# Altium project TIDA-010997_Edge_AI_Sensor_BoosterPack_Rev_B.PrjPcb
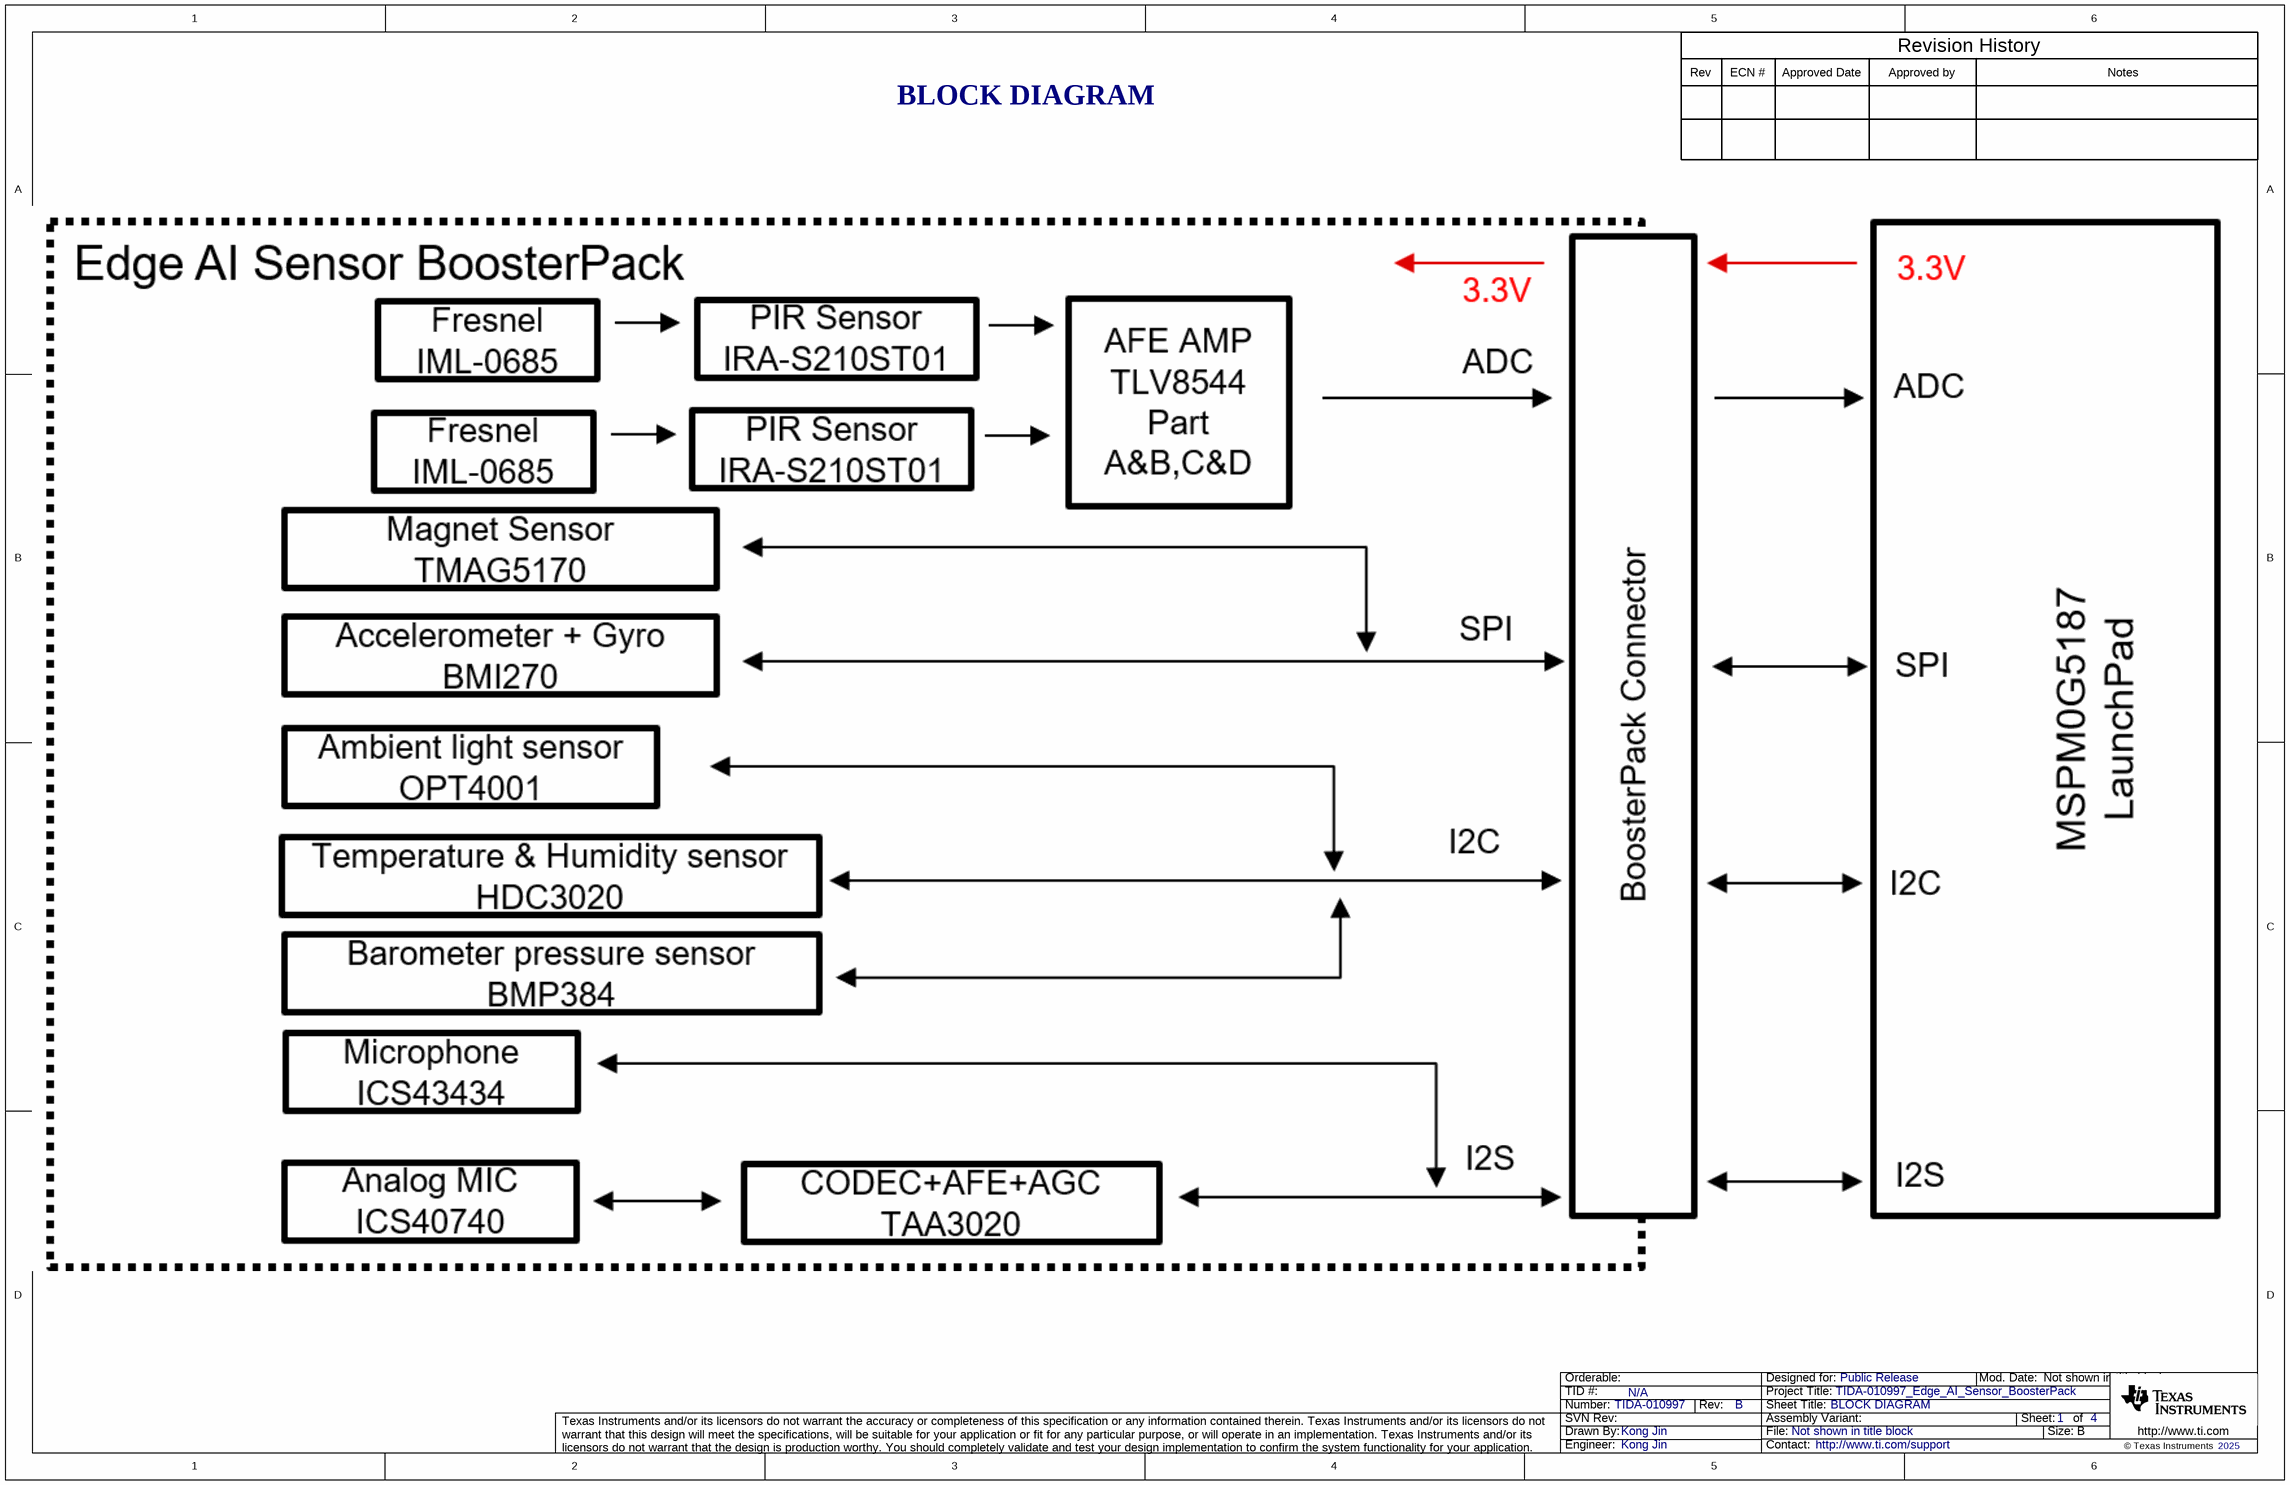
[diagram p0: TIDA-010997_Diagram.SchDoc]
CopyrightYear: 2025; PCB_Layout: Kong Jin; PCB_Rev: B; PRJ_Customer: Public Release; PRJ_Engineer: Kong Jin; PRJ_Number: TIDA-010997; PRJ_Title: TIDA-010997_Edge_AI_Sensor_BoosterPack; SCH_Rev: B; TechSupport: http://www.ti.com/support; TID: N/A
4 sheets, 121 parts. Net scope: global (net labels, ports and power ports of the same name join across sheets).
Board file: TIDA-010997_PCB.PcbDoc
Sheets:
  TIDA-010997_Diagram.SchDoc
  TIDA-010997_Connector.SchDoc
  TIDA-010997_Sensors.SchDoc
  TIDA-010997_Audio_Air_pressure.SchDoc

## Sheet TIDA-010997_Diagram.SchDoc: BLOCK DIAGRAM
size 431 x 279 mm; Date: Not shown in title block; ApprovedBy: Not shown in title block; CheckedBy: Not shown in title block; Author: Not shown in title block; CompanyName: Not shown in title block; DrawnBy: Kong Jin; Organization: Not shown in title block; Address1: Not shown in title block; Address2: Not shown in title block; Address3: Not shown in title block; Address4: Not shown in title block; DocumentNumber: 1; Revision: Use project parameter SCH_Rev; SheetNumber: 1; SheetTotal: 4; PageSetup: Record=PageOptions¦CenterHorizontal=True¦CenterVertical=True¦PrintScale=1.00¦XCorrection=1.00¦YCorrection=1.00¦PrintKind=0¦BorderSize=5000000¦LeftOffset=0¦BottomOffset=0¦Orientation=2¦PaperLength=1000¦PaperWidth=1000¦Scale=100¦PaperSource=15¦PrintQuality=600¦MediaType=1¦DitherType=10¦PaperKind=Letter¦PrintScaleMode=1

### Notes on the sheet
- Rev
- ECN #
- Approved Date
- Approved by
- Revision History
- Notes
- BLOCK DIAGRAM

## Sheet TIDA-010997_Connector.SchDoc: Connector
size 431 x 279 mm; Date: Not shown in title block; ApprovedBy: Not shown in title block; CheckedBy: Not shown in title block; Author: Not shown in title block; CompanyName: Not shown in title block; DrawnBy: Kong Jin; Engineer: Not shown in title block; Organization: Not shown in title block; Address1: Not shown in title block; Address2: Not shown in title block; Address3: Not shown in title block; Address4: Not shown in title block; DocumentNumber: 2; Revision: Use project parameter SCH_Rev; SheetNumber: 2; SheetTotal: 4; PageSetup: Record=PageOptions¦CenterHorizontal=True¦CenterVertical=True¦PrintScale=1.00¦XCorrection=1.00¦YCorrection=1.00¦PrintKind=0¦BorderSize=5000000¦LeftOffset=0¦BottomOffset=0¦Orientation=2¦PaperLength=1000¦PaperWidth=1000¦Scale=100¦PaperSource=15¦PrintQuality=600¦MediaType=1¦DitherType=10¦PaperKind=Letter¦PrintScaleMode=1
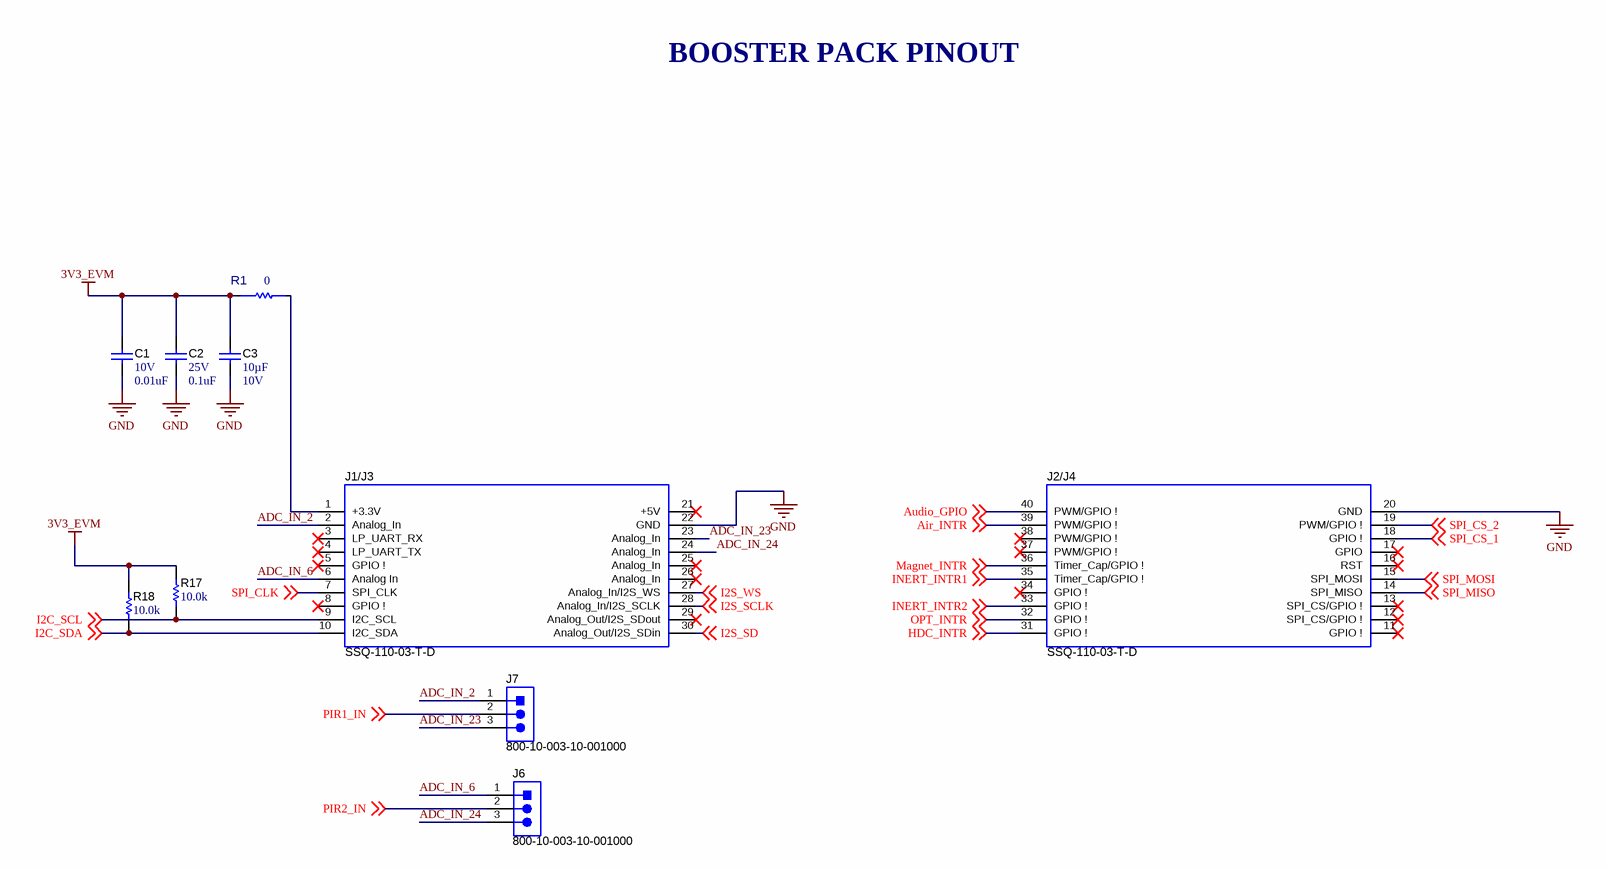
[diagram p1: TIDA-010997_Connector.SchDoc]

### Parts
C1  VDC_V: 10V  ValueDisplayed: 0.01uF  [0402]  (hidden comment: GRM155R61A103KA01D)
C2  VDC_V: 25V  ValueDisplayed: 0.1uF  [0603]  (hidden comment: 06033D104KAT2A)
C3  Cap_F: 10µF  VDC_V: 10V  [0805_HV]  (hidden comment: C2012X7R1A106K125AC)
J1/J3  SSQ-110-03-T-D  [BoosterPack_40pin_J1J3]
J2/J4  SSQ-110-03-T-D  [BoosterPack_40pin_J2J4]
J6  800-10-003-10-001000  [Mill-Max_800-10-003-10-001000]
J7  800-10-003-10-001000  [Mill-Max_800-10-003-10-001000]
R1  value 0  [FP-HCJ0805ZT0R00_0805-MFG]  (hidden comment: HCJ0805ZT0R00)
R17  ValueDisplayed: 10.0k  [0402]  (hidden comment: AC0402FR-0710KL)
R18  ValueDisplayed: 10.0k  [0402]  (hidden comment: AC0402FR-0710KL)

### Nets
3V3_EVM: C1.1 C2.1 C3.1 R1.1 R17.2 R18.2
GND: C1.2 C2.2 C3.2 J1/J3.22(GND) J2/J4.20(GND)
ADC_IN_2: J1/J3.2(Analog_In) J7.1
ADC_IN_6: J1/J3.6(Analog_In) J6.1
ADC_IN_23: J1/J3.23(Analog_In) J7.3
ADC_IN_24: J1/J3.24(Analog_In) J6.3
Air_INTR: J2/J4.39(PWM/GPIO_!) ; off-sheet Air_INTR
Audio_GPIO: J2/J4.40(PWM/GPIO_!) ; off-sheet Audio_GPIO
HDC_INTR: J2/J4.31(GPIO_!) ; off-sheet HDC_INTR
I2C_SCL: J1/J3.9(I2C_SCL) R17.1 ; off-sheet I2C_SCL
I2C_SDA: J1/J3.10(I2C_SDA) R18.1 ; off-sheet I2C_SDA
I2S_SCLK: J1/J3.28(Analog_In/I2S_SCLK) ; off-sheet I2S_SCLK
I2S_SD: J1/J3.30(Analog_Out/I2S_SDin) ; off-sheet I2S_SD
I2S_WS: J1/J3.27(Analog_In/I2S_WS) ; off-sheet I2S_WS
INERT_INTR1: J2/J4.35(Timer_Cap/GPIO_!) ; off-sheet INERT_INTR1
INERT_INTR2: J2/J4.33(GPIO_!) ; off-sheet INERT_INTR2
Magnet_INTR: J2/J4.36(Timer_Cap/GPIO_!) ; off-sheet Magnet_INTR
OPT_INTR: J2/J4.32(GPIO_!) ; off-sheet OPT_INTR
PIR1_IN: J7.2 ; off-sheet PIR1_IN
PIR2_IN: J6.2 ; off-sheet PIR2_IN
SPI_CLK: J1/J3.7(SPI_CLK) ; off-sheet SPI_CLK
SPI_CS_1: J2/J4.18(GPIO_!) ; off-sheet SPI_CS_1
SPI_CS_2: J2/J4.19(PWM/GPIO_!) ; off-sheet SPI_CS_2
SPI_MISO: J2/J4.14(SPI_MISO) ; off-sheet SPI_MISO
SPI_MOSI: J2/J4.15(SPI_MOSI) ; off-sheet SPI_MOSI
NetJ1/J3_1: J1/J3.1(+3.3V) R1.2

Not connected (* = marked no-connect by the designer): J1/J3 3(LP_UART_RX)* 4(LP_UART_TX)* 5(GPIO_!)* 8(GPIO_!)* 21(+5V)* 25(Analog_In)* 26(Analog_In)* 29(Analog_Out/I2S_SDout)*; J2/J4 11(GPIO_!)* 12(SPI_CS/GPIO_!)* 13(SPI_CS/GPIO_!)* 16(RST)* 17(GPIO)* 34(GPIO_!)* 37(PWM/GPIO_!)* 38(PWM/GPIO_!)*

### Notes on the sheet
- BOOSTER PACK PINOUT

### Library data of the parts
C1 = CMP-0006561-2: CAP, CERM, 0.01 uF, 10 V, +/- 10%, X5R, 0402; Manufacturer: MuRata; TaMin_C: -55°C; Polarized: N; SizeAreaWB_mm2: 3; Value1: Unknown; U/M: EA; Value: 0.01uF; TaMax_C: 85°C; SizeZ_mm: 0.6; SizeX_mm: 1; SizeY_mm: 0.5; Cap_F: 10nF; AEC Category: Q200
C2 = CMP-0006758-5: CAP, CERM, 0.1 uF, 25 V, +/- 10%, X5R, 0603; Manufacturer: AVX; TaMin_C: -55°C; ESR_ohm: 48m; Polarized: N; SizeAreaWB_mm2: 4.68; Value1: 0.048 ohm; U/M: EA; Value: 0.1uF; TaMax_C: 85°C; SizeZ_mm: 1; SizeX_mm: 1.6; SizeY_mm: 0.8; SizeArea_mm2: 1.28; Cap_F: 100nF; IRMS_A: 530mA; AEC Category: Q200
C3 = CMP-0007863-2: CAP, CERM, 10 uF, 10 V, +/- 10%, X7R, 0805; Manufacturer: TDK; TaMin_C: -55°C; ESR_ohm: 1.063m; Polarized: N; SizeAreaWB_mm2: 6.75; Value1: 0.001063 ohm; U/M: EA; Value: 10uF; TaMax_C: 125°C; SizeZ_mm: 1.45; SizeX_mm: 2; SizeY_mm: 1.25; Cap_Case: 0805; SizeArea_mm2: 2.5; IRMS_A: 6.3291A; AEC Category: Q200
J1/J3 = CMP-0003837-4: Receptacle, 2.54mm, 10x2, Tin, TH; Alternate PartNumber: CRD-081413-A-G; Manufacturer: Samtec; Alternate Manufacturer: Major League Electronics; Note: Booster Pack 40 pin J1 and J3; Green_Lifecycle: Active; Green_REACh: Incomplete
J2/J4 = CMP-0078266-4: Receptacle, 2.54mm, 10x2, Tin, TH; Alternate PartNumber: CRD-081413-A-G; Manufacturer: Samtec; Alternate Manufacturer: Major League Electronics; Note: Booster Pack 40 pin J2 and J4; Green_REACh: Incomplete; Green_Lifecycle: Active
J6 J7 = CMP-0055086-1: Header, 100mil, 3x1, TH; Manufacturer: Mill-Max; CNHeader: TRUE; Green_Lifecycle: Active; Green_REACh: Passed; CT: FALSE
R1 = CMP-0091603-1: 0 Ohms Jumper 0.5W, 1/2W Chip Resistor 0805 (2012 Metric) Automotive AEC-Q200 Metal Foil; Manufacturer: Stackpole; SizeZ_mm: 0.85mm; Power: 500mW; AEC Grade: Grade 0; AEC Qualified: Yes
R17 R18 = CMP-0077731-1: RES, 10.0 k, 1%, 0.063 W, AEC-Q200 Grade 0, 0402; Manufacturer: Yageo America; Power_W: 63mW; TempCo: 100 ppm/C; Value_Code: 10k0; U/M: EA; Value: 10.0k; EIA_Code: E96; Res_ohm: 10k; SizeX_mm: 1.0; SizeY_mm: 0.5; SizeZ_mm: 0.6; Value2: 0.063W; AEC Qualified: Y; VDC_V: 50V; AEC Grade: 0; AEC Category: Q200

## Sheet TIDA-010997_Sensors.SchDoc: Sensors
size 431 x 279 mm; Date: Not shown in title block; ApprovedBy: Not shown in title block; CheckedBy: Not shown in title block; Author: Not shown in title block; CompanyName: Not shown in title block; DrawnBy: Kong Jin; Engineer: Not shown in title block; Organization: Not shown in title block; Address1: Not shown in title block; Address2: Not shown in title block; Address3: Not shown in title block; Address4: Not shown in title block; DocumentNumber: 3; Revision: Use project parameter SCH_Rev; SheetNumber: 3; SheetTotal: 4; PageSetup: Record=PageOptions¦CenterHorizontal=True¦CenterVertical=True¦PrintScale=1.00¦XCorrection=1.00¦YCorrection=1.00¦PrintKind=0¦BorderSize=5000000¦LeftOffset=0¦BottomOffset=0¦Orientation=2¦PaperLength=1000¦PaperWidth=1000¦Scale=100¦PaperSource=15¦PrintQuality=600¦MediaType=1¦DitherType=10¦PaperKind=Letter¦PrintScaleMode=1
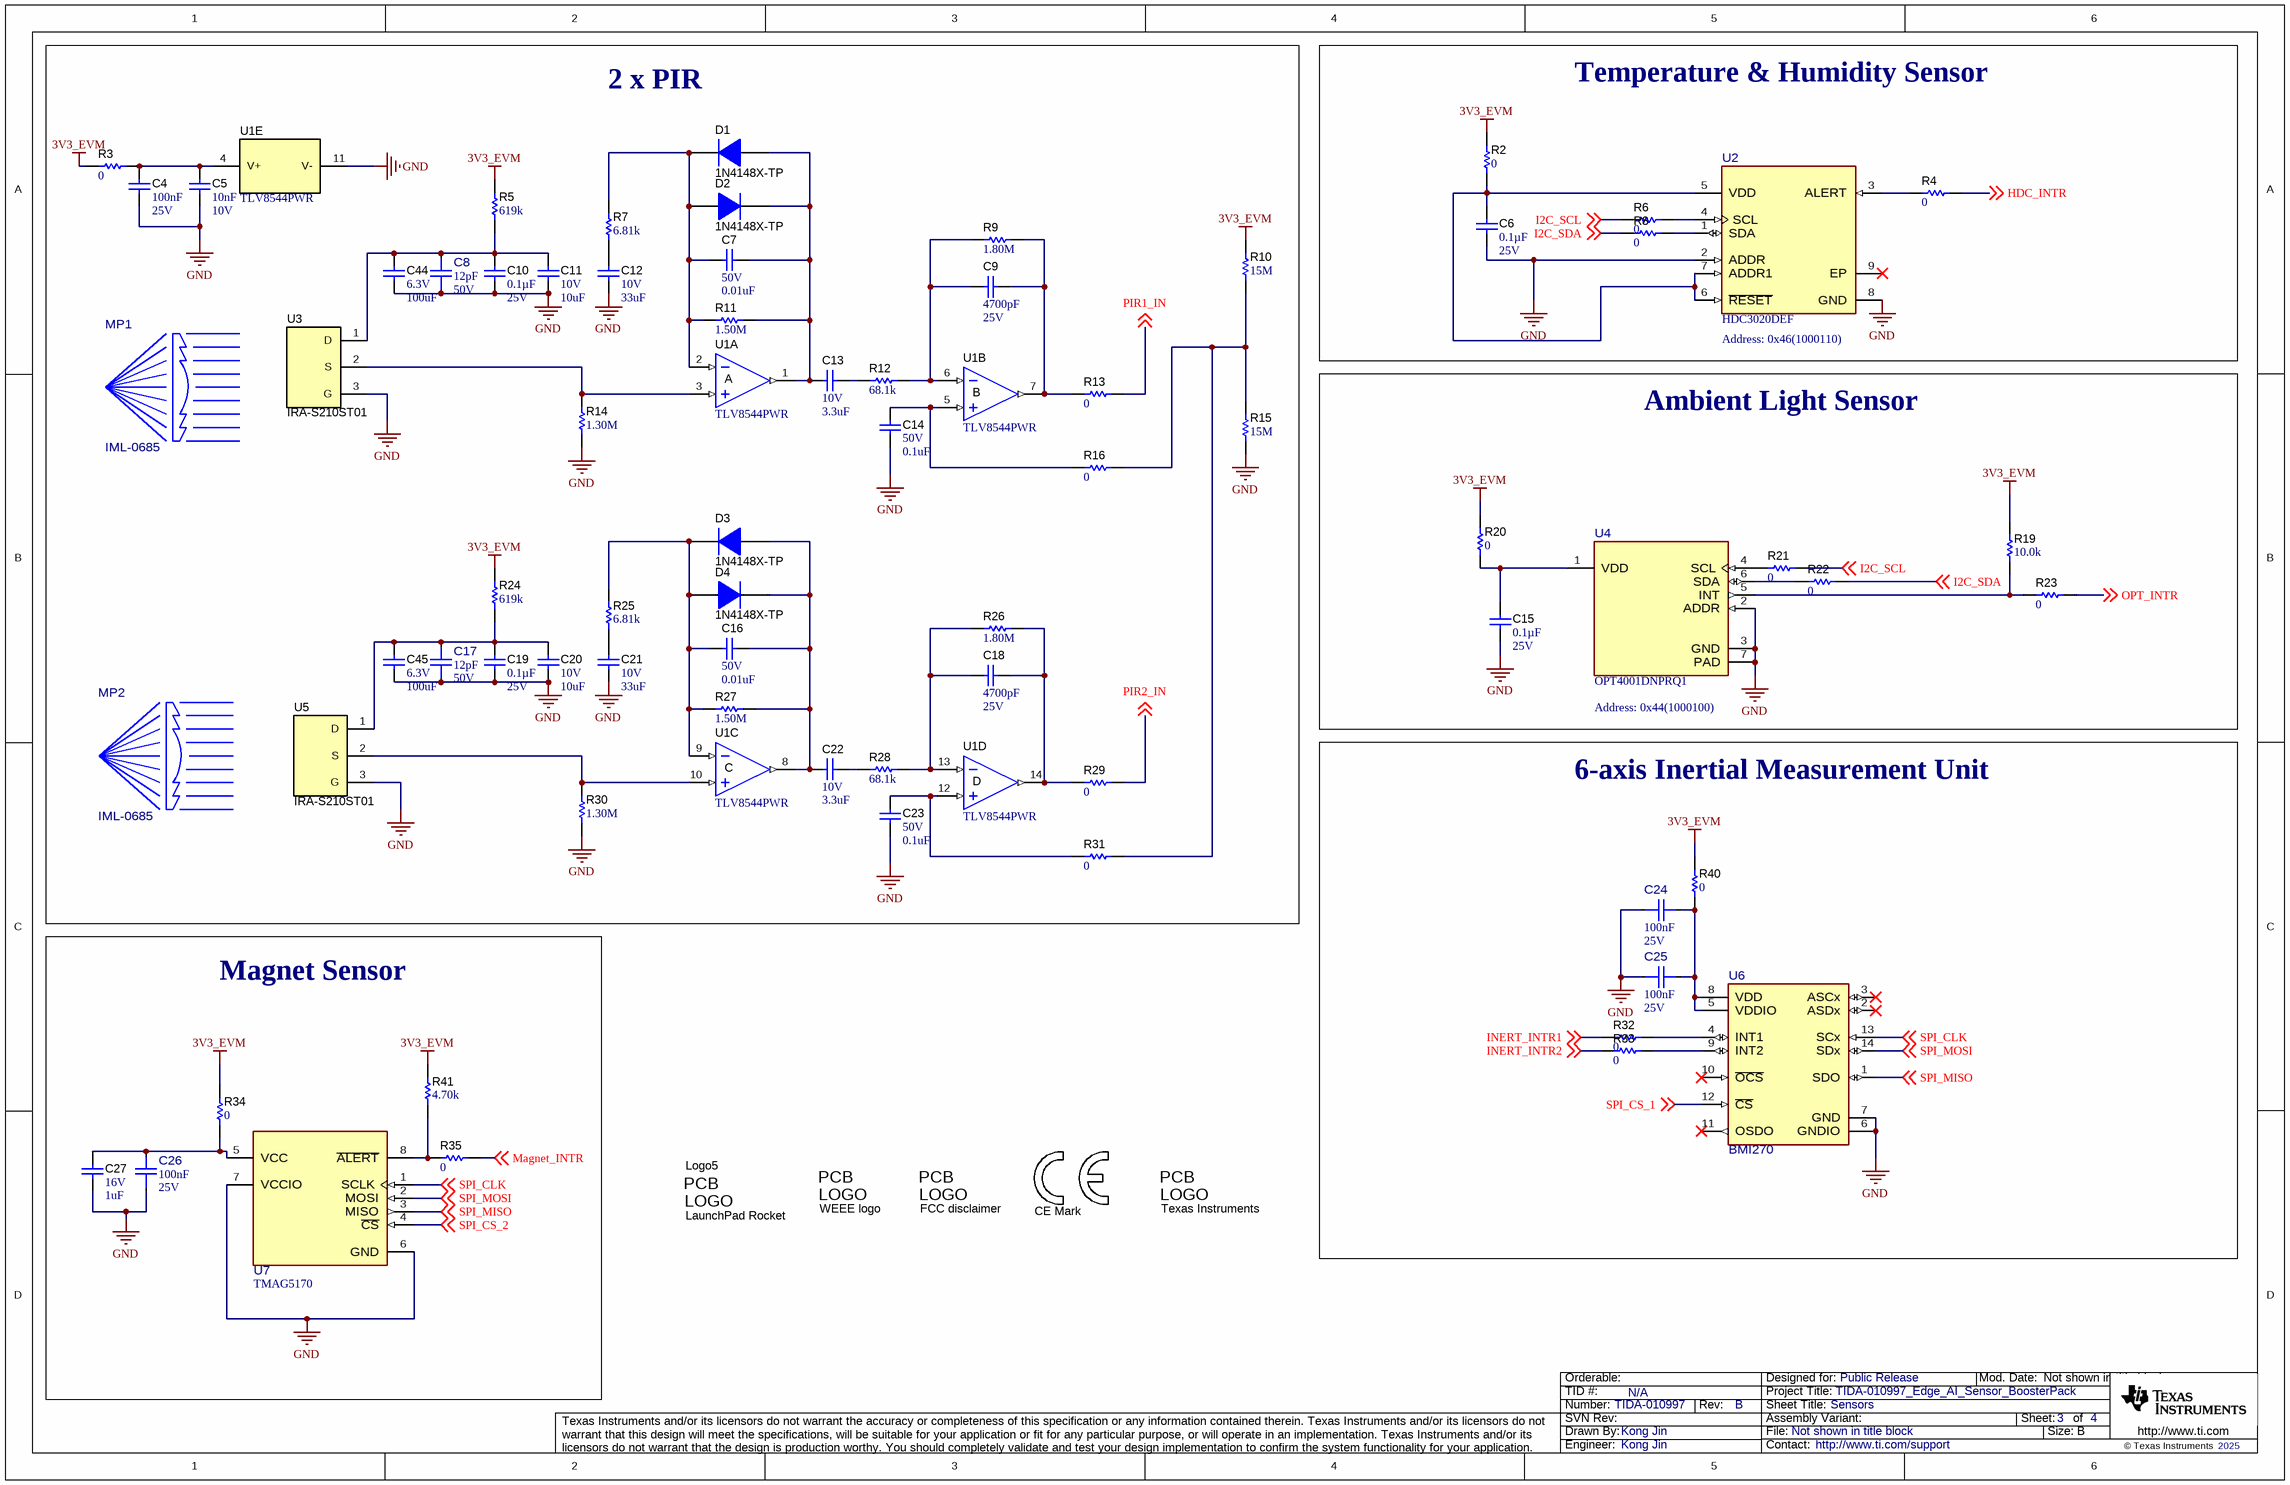
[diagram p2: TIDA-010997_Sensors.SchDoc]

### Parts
C4  Cap_F: 100nF  VDC_V: 25V  [0603]  (hidden comment: C0603C104J3RAC)
C5  Cap_F: 10nF  VDC_V: 10V  [0603]  (hidden comment: 0603ZC103KAT2A)
C6  ValueDisplayed: 0.1µF  VDC_V: 25V  [0402]  (hidden comment: CC0402KRX7R8BB104)
C7  VDC_V: 50V  ValueDisplayed: 0.01uF  [0402]  (hidden comment: GRM155R71H103KA88D)
C8  ValueDisplayed: 12pF  VDC_V: 50V  [FP-GRT1555C1H120JA02D_0402-MFG]  (hidden comment: GRT1555C1H120JA02D)
C9  ValueDisplayed: 4700pF  VDC_V: 25V  [0402]  (hidden comment: CC0402KRX7R8BB472)
C10  ValueDisplayed: 0.1µF  VDC_V: 25V  [0402]  (hidden comment: CC0402KRX7R8BB104)
C11  VDC_V: 10V  ValueDisplayed: 10uF  [0402_070]  (hidden comment: GRM155R61A106ME21D)
C12  VDC_V: 10V  ValueDisplayed: 33uF  [0805_HV]  (hidden comment: C2012X5R1A336M125AC)
C13  VDC_V: 10V  ValueDisplayed: 3.3uF  [0402]  (hidden comment: C1005X5R1A335K050BC)
C14  VDC_V: 50V  ValueDisplayed: 0.1uF  [0402]  (hidden comment: C1005X7R1H104K050BE)
C15  ValueDisplayed: 0.1µF  VDC_V: 25V  [0402]  (hidden comment: CC0402KRX7R8BB104)
C16  VDC_V: 50V  ValueDisplayed: 0.01uF  [0402]  (hidden comment: GRM155R71H103KA88D)
C17  ValueDisplayed: 12pF  VDC_V: 50V  [FP-GRT1555C1H120JA02D_0402-MFG]  (hidden comment: GRT1555C1H120JA02D)
C18  ValueDisplayed: 4700pF  VDC_V: 25V  [0402]  (hidden comment: CC0402KRX7R8BB472)
C19  ValueDisplayed: 0.1µF  VDC_V: 25V  [0402]  (hidden comment: CC0402KRX7R8BB104)
C20  VDC_V: 10V  ValueDisplayed: 10uF  [0402_070]  (hidden comment: GRM155R61A106ME21D)
C21  VDC_V: 10V  ValueDisplayed: 33uF  [0805_HV]  (hidden comment: C2012X5R1A336M125AC)
C22  VDC_V: 10V  ValueDisplayed: 3.3uF  [0402]  (hidden comment: C1005X5R1A335K050BC)
C23  VDC_V: 50V  ValueDisplayed: 0.1uF  [0402]  (hidden comment: C1005X7R1H104K050BE)
C24  ValueDisplayed: 100nF  VDC_V: 25V  [FP-C1608X8R1E104K080AA_0603-MFG]  (hidden comment: C1608X8R1E104K080AA)
C25  ValueDisplayed: 100nF  VDC_V: 25V  [FP-C1608X8R1E104K080AA_0603-MFG]  (hidden comment: C1608X8R1E104K080AA)
C26  ValueDisplayed: 100nF  VDC_V: 25V  [FP-C1608X8R1E104K080AA_0603-MFG]  (hidden comment: C1608X8R1E104K080AA)
C27  VDC_V: 16V  ValueDisplayed: 1uF  [0402]  (hidden comment: C1005X6S1C105K050BC)
C44  VDC_V: 6.3V  ValueDisplayed: 100uF  [1206_190]  (hidden comment: C3216X5R0J107M160AB)
C45  VDC_V: 6.3V  ValueDisplayed: 100uF  [1206_190]  (hidden comment: C3216X5R0J107M160AB)
D1  1N4148X-TP  [SOD-523]
D2  1N4148X-TP  [SOD-523]
D3  1N4148X-TP  [SOD-523]
D4  1N4148X-TP  [SOD-523]
Logo1  CE Mark  [CE_Mark_5mm]  (no BOM)
Logo2  Texas Instruments  [TI_Stacked_Overlay_Small]  (no BOM)
Logo3  FCC disclaimer  [FCC_disclaimer]  (no BOM)
Logo4  WEEE logo  [WEEE_Minimum]  (no BOM)
Logo5  LaunchPad Rocket  [LaunchPadRocket_Small]  (no BOM)
MP1  IML-0685  [FP-IML-0685_LENS_IRA-S-MFG]
MP2  IML-0685  [FP-IML-0685_LENS_IRA-S-MFG]
R2  ValueDisplayed: 0  [0402]  (hidden comment: CRCW04020000Z0ED)
R3  ValueDisplayed: 0  [0402]  (hidden comment: CRCW04020000Z0ED)
R4  ValueDisplayed: 0  [0402]  (hidden comment: CRCW04020000Z0ED)
R5  ValueDisplayed: 619k  [1206]  (hidden comment: CRCW1206619KFKEA)
R6  ValueDisplayed: 0  [0402]  (hidden comment: CRCW04020000Z0ED)
R7  ValueDisplayed: 6.81k  [0402]  (hidden comment: RC0402FR-076K81L)
R8  ValueDisplayed: 0  [0402]  (hidden comment: CRCW04020000Z0ED)
R9  ValueDisplayed: 1.80M  [0805_HV]  (hidden comment: ERJ-6ENF1804V)
R10  ValueDisplayed: 15M  [0805_HV]  (hidden comment: RMCF0805JT15M0)
R11  ValueDisplayed: 1.50M  [0402]  (hidden comment: RC0402FR-071M5L)
R12  ValueDisplayed: 68.1k  [0402]  (hidden comment: CRCW040268K1FKED)
R13  ValueDisplayed: 0  [0402]  (hidden comment: CRCW04020000Z0ED)
R14  ValueDisplayed: 1.30M  [0402]  (hidden comment: CRCW04021M30FKED)
R15  ValueDisplayed: 15M  [0805_HV]  (hidden comment: RMCF0805JT15M0)
R16  ValueDisplayed: 0  [0402]  (hidden comment: CRCW04020000Z0ED)
R19  ValueDisplayed: 10.0k  [0402]  (hidden comment: AC0402FR-0710KL)
R20  ValueDisplayed: 0  [0402]  (hidden comment: CRCW04020000Z0ED)
R21  ValueDisplayed: 0  [0402]  (hidden comment: CRCW04020000Z0ED)
R22  ValueDisplayed: 0  [0402]  (hidden comment: CRCW04020000Z0ED)
R23  ValueDisplayed: 0  [0402]  (hidden comment: CRCW04020000Z0ED)
R24  ValueDisplayed: 619k  [1206]  (hidden comment: CRCW1206619KFKEA)
R25  ValueDisplayed: 6.81k  [0402]  (hidden comment: RC0402FR-076K81L)
R26  ValueDisplayed: 1.80M  [0805_HV]  (hidden comment: ERJ-6ENF1804V)
R27  ValueDisplayed: 1.50M  [0402]  (hidden comment: RC0402FR-071M5L)
R28  ValueDisplayed: 68.1k  [0402]  (hidden comment: CRCW040268K1FKED)
R29  ValueDisplayed: 0  [0402]  (hidden comment: CRCW04020000Z0ED)
R30  ValueDisplayed: 1.30M  [0402]  (hidden comment: CRCW04021M30FKED)
R31  ValueDisplayed: 0  [0402]  (hidden comment: CRCW04020000Z0ED)
R32  ValueDisplayed: 0  [0402]  (hidden comment: CRCW04020000Z0ED)
R33  ValueDisplayed: 0  [0402]  (hidden comment: CRCW04020000Z0ED)
R34  ValueDisplayed: 0  [0402]  (hidden comment: CRCW04020000Z0ED)
R35  ValueDisplayed: 0  [0402]  (hidden comment: CRCW04020000Z0ED)
R40  ValueDisplayed: 0  [0402]  (hidden comment: CRCW04020000Z0ED)
R41  ValueDisplayed: 4.70k  [0402]  (hidden comment: RC0402FR-074K7L)
U1  TLV8544PWR  [PW0014A_N]  (parts A,B,C,D,E of 5)
U2  HDC3020DEF  [DEF0008A-MFG]
U3  IRA-S210ST01  [Murata_IRA-E700ST0]
U4  OPT4001DNPRQ1  [DNP0006A-MFG]
U5  IRA-S210ST01  [Murata_IRA-E700ST0]
U6  BMI270  [FP-BMI270_LGA14-MFG]
U7  TMAG5170A1QDGKR  [DGK0008A-MFG]  (value not drawn)

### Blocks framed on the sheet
2 x PIR: C4 C5 C7-C14 C16-C23 C44 C45 D1-D4 MP1 MP2 R3 R5 R7 R9-R16 R24-R31 U1 U3 U5
Temperature & Humidity Sensor: C6 R2 R4 R6 R8 U2
Ambient Light Sensor: C15 R19-R23 U4
6-axis Inertial Measurement Unit: C24 C25 R32 R33 R40 U6
Magnet Sensor: C26 C27 R34 R35 R41 U7

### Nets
3V3_EVM: R2.2 R3.1 R5.2 R10.2 R19.2 R20.2 R24.2 R34.2 R40.2 R41.2
GND: C4.2 C5.2 C6.2 C8.1 C10.2 C11.2 C12.2 C14.2 C15.2 C17.1 C19.2 C20.2 C21.2 C23.2 C24.1 C25.1 C26.1 C27.2 C44.2 C45.2 R14.1 R15.2 R30.1 U1.11(V-) U2.2(ADDR) U2.8(GND) U3.3(G) U4.2(ADDR) U4.3(GND) U4.7(PAD) U5.3(G) U6.6(GNDIO) U6.7(GND) U7.6(GND) U7.7(VCCIO)
HDC_INTR: R4.2 ; off-sheet HDC_INTR
I2C_SCL: R6.1 R21.2 ; off-sheet I2C_SCL
I2C_SDA: R8.1 R22.2 ; off-sheet I2C_SDA
INERT_INTR1: R32.1 ; off-sheet INERT_INTR1
INERT_INTR2: R33.1 ; off-sheet INERT_INTR2
Magnet_INTR: R35.1 ; off-sheet Magnet_INTR
OPT_INTR: R23.2 ; off-sheet OPT_INTR
PIR1_IN: R13.2 ; off-sheet PIR1_IN
PIR2_IN: R29.2 ; off-sheet PIR2_IN
SPI_CLK: U6.13(SCx) U7.1(SCLK) ; off-sheet SPI_CLK
SPI_CS_1: U6.12(~{CS}) ; off-sheet SPI_CS_1
SPI_CS_2: U7.4(~{CS}) ; off-sheet SPI_CS_2
SPI_MISO: U6.1(SDO) U7.3(MISO) ; off-sheet SPI_MISO
SPI_MOSI: U6.14(SDx) U7.2(MOSI) ; off-sheet SPI_MOSI
NetC4_1: C4.1 C5.1 R3.2 U1.4(V+)
NetC6_1: C6.1 R2.1 U2.5(VDD) U2.6(~{RESET}) U2.7(ADDR1)
NetC7_1: C7.1 C13.2 D1.2(A) D2.1(K) R11.2 U1.1(OUT)
NetC7_2: C7.2 D1.1(K) D2.2(A) R7.2 R11.1 U1.2(IN-)
NetC8_2: C8.2 C10.1 C11.1 C44.1 R5.1 U3.1(D)
NetC9_1: C9.1 R9.2 R13.1 U1.7(OUT)
NetC9_2: C9.2 R9.1 R12.2 U1.6(IN-)
NetC12_1: C12.1 R7.1
NetC13_1: C13.1 R12.1
NetC14_1: C14.1 R16.1 U1.5(IN+)
NetC15_1: C15.1 R20.1 U4.1(VDD)
NetC16_1: C16.1 C22.2 D3.2(A) D4.1(K) R27.2 U1.8(OUT)
NetC16_2: C16.2 D3.1(K) D4.2(A) R25.2 R27.1 U1.9(IN-)
NetC17_2: C17.2 C19.1 C20.1 C45.1 R24.1 U5.1(D)
NetC18_1: C18.1 R26.2 R29.1 U1.14(OUT)
NetC18_2: C18.2 R26.1 R28.2 U1.13(IN-)
NetC21_1: C21.1 R25.1
NetC22_1: C22.1 R28.1
NetC23_1: C23.1 R31.1 U1.12(IN+)
NetC24_2: C24.2 C25.2 R40.1 U6.5(VDDIO) U6.8(VDD)
NetC26_2: C26.2 C27.1 R34.1 U7.5(VCC)
NetR4_1: R4.1 U2.3(ALERT)
NetR6_2: R6.2 U2.4(SCL)
NetR8_2: R8.2 U2.1(SDA)
NetR10_1: R10.1 R15.1 R16.2 R31.2
NetR14_2: R14.2 U1.3(IN+) U3.2(S)
NetR19_1: R19.1 R23.1 U4.5(INT)
NetR21_1: R21.1 U4.4(SCL)
NetR22_1: R22.1 U4.6(SDA)
NetR30_2: R30.2 U1.10(IN+) U5.2(S)
NetR32_2: R32.2 U6.4(INT1)
NetR33_2: R33.2 U6.9(INT2)
NetR35_2: R35.2 R41.1 U7.8(~{ALERT})

Not connected (* = marked no-connect by the designer): U2 9(EP)*; U6 2(ASDx)* 3(ASCx)* 10(~{OCS})* 11(OSDO)*

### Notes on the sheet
- (near U2) Address: 0x46(1000110)
- (near U4) Address: 0x44(1000100)
- (near U7) TMAG5170

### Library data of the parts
C4 = CMP-0006855-4: CAP, CERM, 0.1 uF, 25 V, +/- 5%, X7R, 0603; Manufacturer: Kemet; TaMin_C: -55°C; Polarized: N; SizeAreaWB_mm2: 4.68; Value1: Unknown; U/M: EA; Value: 0.1uF; TaMax_C: 125°C; SizeZ_mm: 1; SizeX_mm: 1.6; SizeY_mm: 0.8; SizeArea_mm2: 1.28; AEC Category: Q200
C5 = CMP-0006814-5: CAP, CERM, 0.01 uF, 10 V, +/- 10%, X7R, 0603; Manufacturer: AVX; TaMin_C: -55°C; Polarized: N; SizeAreaWB_mm2: 4.68; Value1: Unknown; U/M: EA; Value: 0.01uF; TaMax_C: 125°C; SizeZ_mm: 1; SizeX_mm: 1.6; SizeY_mm: 0.8; SizeArea_mm2: 1.28; AEC Category: Q200
C6 C10 C15 C19 = CMP-0860555-1: CAP, CERM, 0.1 µF, 25 V,+/- 10%, X7R, 0402; Manufacturer: Yageo; SizeArea_mm2: 0.5; AEC Qualified: N; SizeX_mm: 1; U/M: EA; Value: 0.1uF; TaMin_C: -55°C; SizeZ_mm: 0.6; Cap_F: 100nF; TaMax_C: 125°C; SizeAreaWB_mm2: 3; AEC Category: Q200
C7 C16 = CMP-0006674-2: CAP, CERM, 0.01 uF, 50 V, +/- 10%, X7R, 0402; Manufacturer: MuRata; TaMin_C: -55°C; Polarized: N; SizeAreaWB_mm2: 3; Value1: Unknown; U/M: EA; Value: 0.01uF; TaMax_C: 125°C; SizeZ_mm: 0.6; SizeX_mm: 1; SizeY_mm: 0.5; Cap_F: 10nF; AEC Category: Q200
C8 C17 = CMP-0120209-1: Multi-Layer Ceramic Capacitor 12pF 50V C0G ±5% 0402 Paper T/R; Manufacturer: Murata; AEC Grade: Grade 1; AEC Qualified: Yes; SizeZ_mm: 0.55mm; TempCo: 30ppm/°C
C9 C18 = CMP-0860557-1: CAP, CERM, 4700 pF, 25 V,+/- 10%, X7R, 0402; Manufacturer: Yageo; Polarized: N; SizeY_mm: 0.5; Green_Lifecycle: Active; Value: 4700pF; TaMin_C: -55°C; TaMax_C: 125°C; SizeZ_mm: 0.6; U/M: EA; SizeAreaWB_mm2: 3; Cap_F: 4.7nF; SizeX_mm: 1; AEC Category: Q200; Green_REACh: Passed
C11 C20 = CMP-0006565-2: CAP, CERM, 10 uF, 10 V, +/- 20%, X5R, 0402; Manufacturer: MuRata; TaMin_C: -55°C; Polarized: N; SizeAreaWB_mm2: 3; Value1: Unknown; U/M: EA; Value: 10uF; TaMax_C: 85°C; SizeZ_mm: 0.7; SizeX_mm: 1; SizeY_mm: 0.5; Cap_Case: 0402; Cap_F: 10µF; AEC Category: Q200
C12 C21 = CMP-0007824-2: CAP, CERM, 33 uF, 10 V, +/- 20%, X5R, 0805; Manufacturer: TDK; TaMin_C: -55°C; ESR_ohm: 1.694m; Polarized: N; SizeAreaWB_mm2: 6.75; Value1: 0.001694 ohm; U/M: EA; Value: 33uF; TaMax_C: 85°C; SizeZ_mm: 1.45; SizeX_mm: 2; SizeY_mm: 1.25; Cap_Case: 0805; SizeArea_mm2: 2.5; Cap_F: 33µF; IRMS_A: 5.01281A; AEC Category: Q200
C13 C22 = CMP-0006265-2: CAP, CERM, 3.3 uF, 10 V, +/- 10%, X5R, 0402; Manufacturer: TDK; TaMin_C: -55°C; ESR_ohm: 4.157m; Polarized: N; SizeAreaWB_mm2: 3; Value1: 0.004157 ohm; U/M: EA; Value: 3.3uF; TaMax_C: 85°C; SizeZ_mm: 0.6; SizeX_mm: 1; SizeY_mm: 0.5; Cap_F: 3.3µF; IRMS_A: 2.45391A; AEC Category: Q200
C14 C23 = CMP-0064946-2: CAP, CERM, 0.1 uF, 50 V,+/- 10%, X7R, 0402; Manufacturer: TDK; TaMin_C: -55°C; Polarized: N; SizeAreaWB_mm2: 3; Value1: Unknown; U/M: EA; Value: 0.1uF; TaMax_C: 125°C; SizeZ_mm: 0.6; SizeX_mm: 1; SizeY_mm: 0.5; Cap_F: 100nF; AEC Category: Q200
C24-C26 = CMP-0089959-1: 0.1µF ±10% 25V Ceramic Capacitor X8R 0603 (1608 Metric); Manufacturer: TDK Corporation; SizeZ_mm: 0.9mm; TempCo: 15%; AEC Qualified: No; Value: 100nF
C27 = CMP-0006286-2: CAP, CERM, 1 uF, 16 V, +/- 10%, X6S, 0402; Manufacturer: TDK; TaMin_C: -55°C; ESR_ohm: 0.011416; Polarized: N; SizeAreaWB_mm2: 3; Value1: 0.011416 ohm; U/M: EA; Value: 1uF; TaMax_C: 105°C; SizeZ_mm: 0.6; SizeX_mm: 1; SizeY_mm: 0.5; Cap_F: 1µF; IRMS_A: 1.483A; AEC Category: Q200
C44 C45 = CMP-0064957-2: CAP, CERM, 100 uF, 6.3 V,+/- 20%, X5R, 1206; Manufacturer: TDK; TaMin_C: -55°C; Polarized: N; SizeAreaWB_mm2: 10.92; Value1: Unknown; U/M: EA; Value: 100uF; TaMax_C: 85°C; SizeZ_mm: 1.9; SizeX_mm: 3.2; SizeY_mm: 1.6; Cap_Case: 1206; SizeArea_mm2: 5.12; Cap_F: 100µF; AEC Category: Q200
D1-D4 = CMP-0076957-3: Diode, Switching, 75 V, 0.3 A, SOD-523; Manufacturer: Micro Commercial Components; SizeY_mm: 0.9; Value2: 1.25V; Vr_V: 75V; Value1: 0.3A; Value: 75V; Green_Lifecycle: Not Set; SizeAreaWB_mm2: 5.13; SizeArea_mm2: 1.53; SizeZ_mm: 0.65; Io_A: 300mA; TJmax_C: 150°C; SizeX_mm: 1.7; Green_REACh: Incomplete; AEC Category: Q101
Logo1 = CMP-0074844-2: Manufacturer: Texas Instruments; SymbolCreator: a0412235; AEC Category: Q200; CompType: IC
Logo2 = CMP-0074838-1: Texas Instrument Corporate Signature; SymbolCreator: a0412235; Lib Reference: TI_Logo; Library Reference: Logo
Logo3 = CMP-0074847-1: FCC_disclaimer; Library Reference: Logo
Logo4 = CMP-0074769-4: Manufacturer: Texas Instruments; CompType: IC; AEC Category: Q200
Logo5 = CMP-0074846-1: LaunchPad Rocket logo; Lib Reference: LaunchPad_Rocket; SymbolCreator: a0412235
MP1 MP2 = CMP-0091003-1: Fresnel Lens, IML Series, Pyroelectric Infrared Sensors, Inline Type; Manufacturer: Murata; SizeZ_mm: 8.75mm; AEC Qualified: No
R2-R4 R6 R8 R13 R16 R20-R23 R29 R31-R35 R40 = CMP-0026822-3: RES, 0, 5%, 0.063 W, AEC-Q200 Grade 0, 0402; Manufacturer: Vishay-Dale; Power_W: 63mW; TempCo: 200 ppm/C; Value_Code: 0000; Value: 0; EIA_Code: E24; SizeX_mm: 1; SizeY_mm: 0.5; SizeZ_mm: 0.6; Value2: 0.063W; AEC Qualified: Y; VDC_V: 50V; AEC Category: Q200
R5 R24 = CMP-0017103-3: RES, 619 k, 1%, 0.25 W, AEC-Q200 Grade 0, 1206; Manufacturer: Vishay-Dale; Power_W: 250mW; TempCo: 100 ppm/C; Value: 619k; EIA_Code: E96; SizeX_mm: 3.2; SizeY_mm: 1.6; SizeZ_mm: 1.35; Value2: 0.25W; SizeArea_mm2: 5.12; AEC Qualified: Y; VDC_V: 200V; AEC Category: Q200; AEC Grade: 0
R7 R25 = CMP-0078787-1: RES, 6.81 k, 1%, 0.063 W, 0402; Manufacturer: Yageo America; Value_Code: 6k81; SizeArea_mm2: 0.5; AEC Qualified: N; AEC Category: Q200; Value: 6.81k; SizeZ_mm: 0.6; EIA_Code: E96; TempCo: 100 ppm/C; Power_W: 63mW; VDC_V: 50V; Value2: 0.063W; SizeX_mm: 1
R9 R26 = CMP-0021600-3: RES, 1.80 M, 1%, 0.125 W, AEC-Q200 Grade 0, 0805; Manufacturer: Panasonic; Power_W: 125mW; TempCo: 100 ppm/C; Value_Code: 1M80; Value: 1.80Meg; Res_ohm: 1.8M; SizeX_mm: 2; SizeY_mm: 1.25; SizeZ_mm: 1.45; Value2: 0.125W; SizeArea_mm2: 2.5; AEC Qualified: Y; AEC Category: Q200; AEC Grade: 0; SizeAreaWB_mm2: 6.75
R10 R15 = CMP-0020831-2: RES, 15 M, 5%, 0.125 W, AEC-Q200 Grade 0, 0805; Manufacturer: Stackpole Electronics Inc; Power_W: 125mW; TempCo: 200 ppm/C; Value_Code: 15M0; U/M: EA; Value: 15Meg; SizeX_mm: 2; SizeY_mm: 1.25; SizeZ_mm: 1.45; Value2: 0.125W; SizeArea_mm2: 2.5; AEC Qualified: Y; VDC_V: 75V; AEC Grade: 0; AEC Category: Q200
R11 R27 = CMP-0026726-1: RES, 1.50 M, 1%, 0.063 W, 0402; Manufacturer: Yageo America; Power_W: 63mW; TempCo: 100 ppm/C; Value_Code: 1M50; U/M: EA; Value: 1.50Meg; EIA_Code: E96; Res_ohm: 1.5M; SizeX_mm: 1; SizeY_mm: 0.5; SizeZ_mm: 0.6; Value2: 0.063W; AEC Qualified: N; VDC_V: 50V; AEC Category: Q200
R12 R28 = CMP-0026506-2: RES, 68.1 k, 1%, 0.063 W, AEC-Q200 Grade 0, 0402; Manufacturer: Vishay-Dale; Power_W: 63mW; TempCo: 100 ppm/C; Value_Code: 68k1; Value: 68.1k; EIA_Code: E96; SizeX_mm: 1; SizeY_mm: 0.5; SizeZ_mm: 0.6; Value2: 0.063W; AEC Qualified: Y; VDC_V: 50V; AEC Category: Q200; AEC Grade: 0
R14 R30 = CMP-0026111-2: RES, 1.30 M, 1%, 0.063 W, AEC-Q200 Grade 0, 0402; Manufacturer: Vishay-Dale; Power_W: 63mW; TempCo: 100 ppm/C; Value_Code: 1M30; Value: 1.30Meg; EIA_Code: E96; Res_ohm: 1.3M; SizeX_mm: 1; SizeY_mm: 0.5; SizeZ_mm: 0.6; Value2: 0.063W; AEC Qualified: Y; VDC_V: 50V; AEC Category: Q200; AEC Grade: 0
R19 = CMP-0077731-1: as R17 on sheet TIDA-010997_Connector
R41 = CMP-0026739-1: RES, 4.70 k, 1%, 0.0625 W, 0402; Manufacturer: Yageo America; Power_W: 62.5mW; TempCo: 100 ppm/C; Value_Code: 4k70; U/M: EA; Value: 4.70k; Res_ohm: 4.7k; SizeX_mm: 1; SizeY_mm: 0.5; SizeZ_mm: 0.6; AEC Qualified: N; VDC_V: 50V; AEC Category: Q200
U1 = CMP-0013616-3: 500 nA RRIO Nanopower Operational Amplifier, PW0014A (TSSOP-14); Manufacturer: Texas Instruments; Alternate PartNumber: TLV8544PWT; SizeX_mm: 6.4; SizeY_mm: 5; CompType: IC; SizeZ_mm: 1.2; SizeArea_mm2: 32; SizeAreaWB_mm2: 58.8; U/M: EA
U2 = CMP-0087942-2: Integrated Humidity and Temperature Digital Sensor; Manufacturer: Texas Instruments; AEC Category: Q200; AEC Qualified: No; SizeZ_mm: 0.8mm; CompType: IC
U3 U5 = CMP-0080109-2: Pyro Electric Infrared Sensor Fresnel Lens, TH; Manufacturer: MuRata; SizeArea_mm2: 84.64; SizeAreaWB_mm2: 125.44; SizeY_mm: 9.2; SizeZ_mm: 4.9
U4 = CMP-0096079-1: High Speed, High Precision, Digital Ambient Light Sensor; Manufacturer: Texas Instruments; Min Supply Voltage: 1.6V; Sensor Output: I2C,SMBus; Standoff Height: 0mm; AEC Qualified: No; Max Supply Voltage: 3.6V; TJmax_C: +85°C; SizeZ_mm: 0.65mm; Operating Supply Current: 1.6-30uA
U6 = CMP-0126507-1: Accelerometer, Gyroscope, 6 Axis Sensor I2C, SPI Output; Manufacturer: Bosch Sensortec; SizeZ_mm: 0.87mm; Accel Range: 2-16g; Accel Resolution: 16bits; Accel Sensitivity: 16384LSB/g; AEC Qualified: No; Gyro Range: 125-2000°/s; Gyro Sensitivity: 262.144LSB/°/s; Max Supply Voltage: 3.6V; Min Supply Voltage: 1.2V; Operating Supply Current: 3-970uA; Standoff Height: 0.11mm; TaMax_C: +85°C; TaMin_C: -40°C
U7 = CMP-0088287-1: 3-Axis Linear Hall Effect Sensor With SPI Interface; Manufacturer: Texas Instruments; TJmax_C: +170°C; SizeZ_mm: 1.1mm; Operating Supply Current: 0.000005-4mA; Standoff Height: 0.05mm; Min Supply Voltage: 1.65V; Max Supply Voltage: 5.5V; AEC Grade: Grade 0; AEC Qualified: Yes

## Sheet TIDA-010997_Audio_Air_pressure.SchDoc: Audio_Air Pressure sensor
size 431 x 279 mm; Date: Not shown in title block; ApprovedBy: Not shown in title block; CheckedBy: Not shown in title block; Author: Not shown in title block; CompanyName: Not shown in title block; DrawnBy: Kong Jin; Engineer: Not shown in title block; Organization: Not shown in title block; Address1: Not shown in title block; Address2: Not shown in title block; Address3: Not shown in title block; Address4: Not shown in title block; DocumentNumber: 2; Revision: Use project parameter SCH_Rev; SheetNumber: 4; SheetTotal: 4; PageSetup: Record=PageOptions¦CenterHorizontal=True¦CenterVertical=True¦PrintScale=1.00¦XCorrection=1.00¦YCorrection=1.00¦PrintKind=0¦BorderSize=5000000¦LeftOffset=0¦BottomOffset=0¦Orientation=2¦PaperLength=1000¦PaperWidth=1000¦Scale=100¦PaperSource=15¦PrintQuality=600¦MediaType=1¦DitherType=10¦PaperKind=Letter¦PrintScaleMode=1
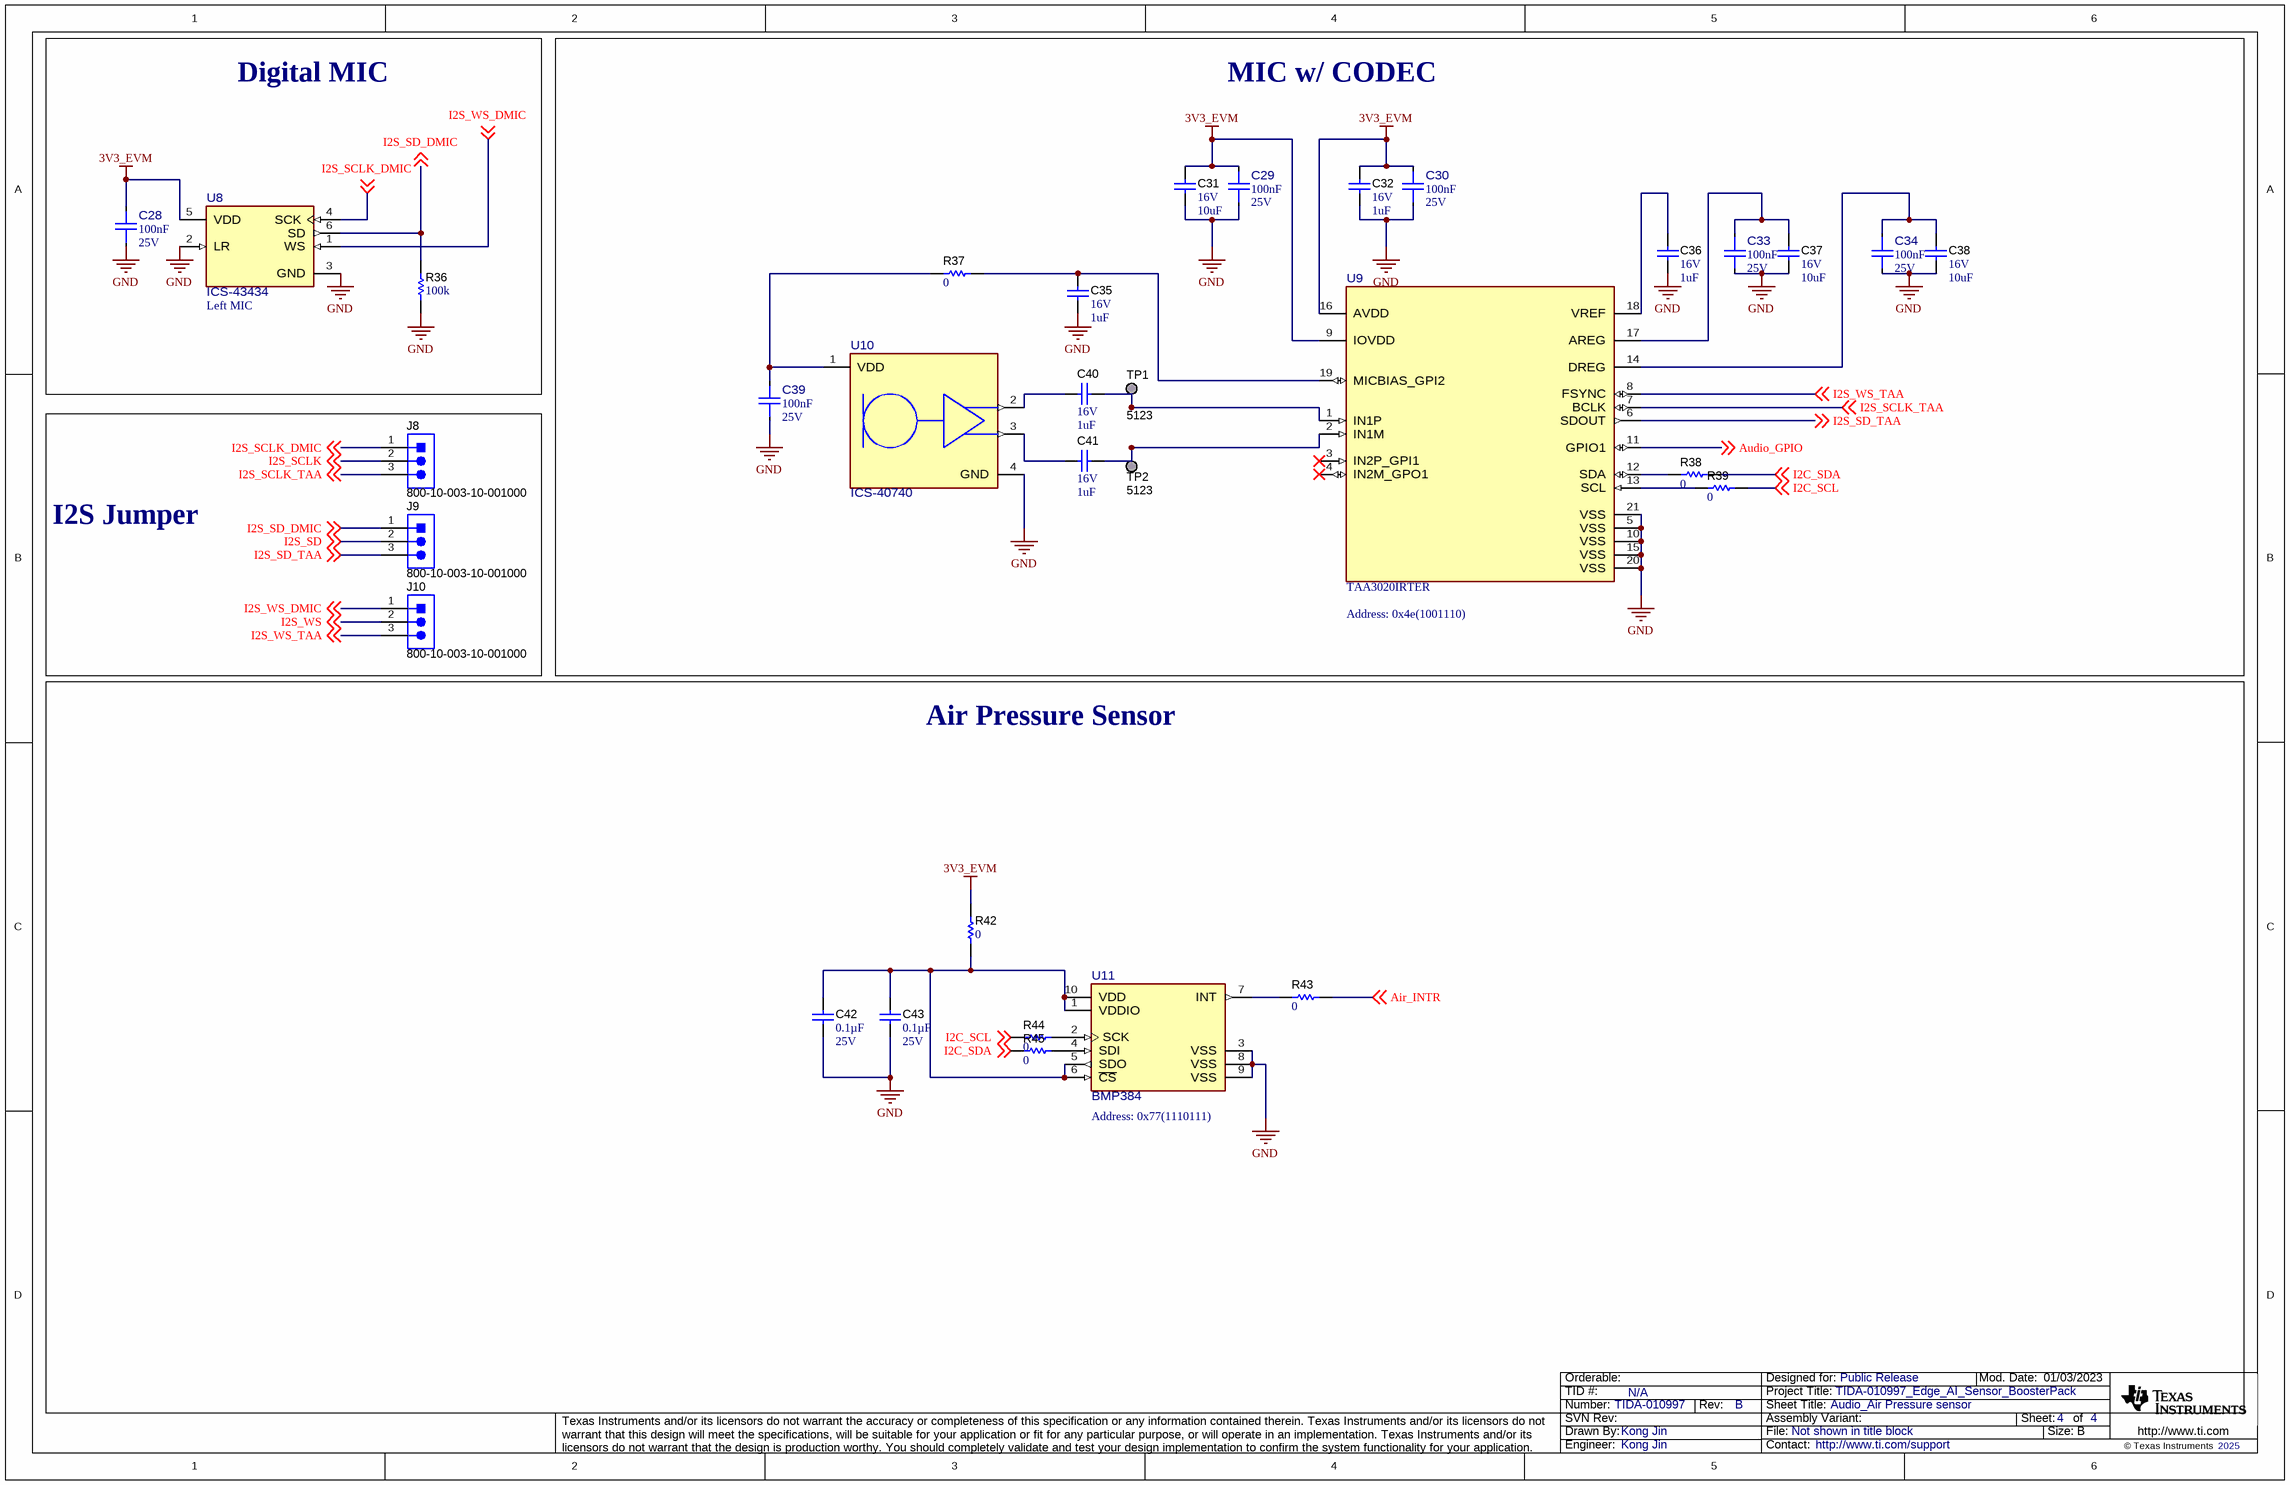
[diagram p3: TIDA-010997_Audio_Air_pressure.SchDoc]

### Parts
C28  ValueDisplayed: 100nF  VDC_V: 25V  [FP-C1608X8R1E104K080AA_0603-MFG]  (hidden comment: C1608X8R1E104K080AA)
C29  ValueDisplayed: 100nF  VDC_V: 25V  [FP-C1608X8R1E104K080AA_0603-MFG]  (hidden comment: C1608X8R1E104K080AA)
C30  ValueDisplayed: 100nF  VDC_V: 25V  [FP-C1608X8R1E104K080AA_0603-MFG]  (hidden comment: C1608X8R1E104K080AA)
C31  VDC_V: 16V  ValueDisplayed: 10uF  [0603]  (hidden comment: GRM188R61C106MAALD)
C32  VDC_V: 16V  ValueDisplayed: 1uF  [0402]  (hidden comment: C1005X6S1C105K050BC)
C33  ValueDisplayed: 100nF  VDC_V: 25V  [FP-C1608X8R1E104K080AA_0603-MFG]  (hidden comment: C1608X8R1E104K080AA)
C34  ValueDisplayed: 100nF  VDC_V: 25V  [FP-C1608X8R1E104K080AA_0603-MFG]  (hidden comment: C1608X8R1E104K080AA)
C35  VDC_V: 16V  ValueDisplayed: 1uF  [0402]  (hidden comment: C1005X6S1C105K050BC)
C36  VDC_V: 16V  ValueDisplayed: 1uF  [0402]  (hidden comment: C1005X6S1C105K050BC)
C37  VDC_V: 16V  ValueDisplayed: 10uF  [0603]  (hidden comment: GRM188R61C106MAALD)
C38  VDC_V: 16V  ValueDisplayed: 10uF  [0603]  (hidden comment: GRM188R61C106MAALD)
C39  ValueDisplayed: 100nF  VDC_V: 25V  [FP-C1608X8R1E104K080AA_0603-MFG]  (hidden comment: C1608X8R1E104K080AA)
C40  VDC_V: 16V  ValueDisplayed: 1uF  [0402]  (hidden comment: C1005X6S1C105K050BC)
C41  VDC_V: 16V  ValueDisplayed: 1uF  [0402]  (hidden comment: C1005X6S1C105K050BC)
C42  ValueDisplayed: 0.1µF  VDC_V: 25V  [0402]  (hidden comment: CC0402KRX7R8BB104)
C43  ValueDisplayed: 0.1µF  VDC_V: 25V  [0402]  (hidden comment: CC0402KRX7R8BB104)
J8  800-10-003-10-001000  [Mill-Max_800-10-003-10-001000]
J9  800-10-003-10-001000  [Mill-Max_800-10-003-10-001000]
J10  800-10-003-10-001000  [Mill-Max_800-10-003-10-001000]
R36  ValueDisplayed: 100k  [0402]  (hidden comment: RC1005F104CS)
R37  ValueDisplayed: 0  [0402]  (hidden comment: CRCW04020000Z0ED)
R38  ValueDisplayed: 0  [0402]  (hidden comment: CRCW04020000Z0ED)
R39  ValueDisplayed: 0  [0402]  (hidden comment: CRCW04020000Z0ED)
R42  ValueDisplayed: 0  [0402]  (hidden comment: CRCW04020000Z0ED)
R43  ValueDisplayed: 0  [0402]  (hidden comment: CRCW04020000Z0ED)
R44  ValueDisplayed: 0  [0402]  (hidden comment: CRCW04020000Z0ED)
R45  ValueDisplayed: 0  [0402]  (hidden comment: CRCW04020000Z0ED)
TP1  5123  [Keystone_5123]
TP2  5123  [Keystone_5123]
U8  ICS-43434  [FP-ICS-43434_LGA_CAV6-MFG]
U9  TAA3020IRTER  [RTE0020A-MFG]
U10  ICS-40740  [FP-ICS-40740_LGA4-MFG]
U11  BMP384  [FP-BMP384_LGA10-MFG]

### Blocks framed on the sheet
Digital MIC: C28 R36 U8
MIC w/ CODEC: C29-C41 R37-R39 TP1 TP2 U9 U10
I2S Jumper: J8-J10
Air Pressure Sensor: C42 C43 R42-R45 U11

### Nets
3V3_EVM: C28.2 C29.2 C30.2 C31.1 C32.1 R42.2 U8.5(VDD) U9.9(IOVDD) U9.16(AVDD)
GND: C28.1 C29.1 C30.1 C31.2 C32.2 C33.2 C34.2 C35.2 C36.2 C37.1 C38.1 C39.1 C42.2 C43.2 R36.1 U8.2(LR) U8.3(GND) U9.5(VSS) U9.10(VSS) U9.15(VSS) U9.20(VSS) U9.21(VSS) U10.4(GND) U11.3(VSS) U11.8(VSS) U11.9(VSS)
Air_INTR: R43.2 ; off-sheet Air_INTR
Audio_GPIO: U9.11(GPIO1) ; off-sheet Audio_GPIO
I2C_SCL: R39.2 R44.1 ; off-sheet I2C_SCL
I2C_SDA: R38.2 R45.1 ; off-sheet I2C_SDA
I2S_SCLK: J8.2 ; off-sheet I2S_SCLK
I2S_SCLK_DMIC: J8.1 U8.4(SCK) ; off-sheet I2S_SCLK_DMIC
I2S_SCLK_TAA: J8.3 U9.7(BCLK) ; off-sheet I2S_SCLK_TAA
I2S_SD: J9.2 ; off-sheet I2S_SD
I2S_SD_DMIC: J9.1 R36.2 U8.6(SD) ; off-sheet I2S_SD_DMIC
I2S_SD_TAA: J9.3 U9.6(SDOUT) ; off-sheet I2S_SD_TAA
I2S_WS: J10.2 ; off-sheet I2S_WS
I2S_WS_DMIC: J10.1 U8.1(WS) ; off-sheet I2S_WS_DMIC
I2S_WS_TAA: J10.3 U9.8(FSYNC) ; off-sheet I2S_WS_TAA
NetC33_1: C33.1 C37.2 U9.17(AREG)
NetC34_1: C34.1 C38.2 U9.14(DREG)
NetC35_1: C35.1 R37.2 U9.19(MICBIAS_GPI2)
NetC36_1: C36.1 U9.18(VREF)
NetC39_2: C39.2 R37.1 U10.1(VDD)
NetC40_1: C40.1 U10.2(OUTPUT+)
NetC40_2: C40.2 TP1.1 U9.1(IN1P)
NetC41_1: C41.1 U10.3(OUTPUT-)
NetC41_2: C41.2 TP2.1 U9.2(IN1M)
NetC42_1: C42.1 C43.1 R42.1 U11.1(VDDIO) U11.5(SDO) U11.6(~{CS}) U11.10(VDD)
NetR38_1: R38.1 U9.12(SDA)
NetR39_1: R39.1 U9.13(SCL)
NetR43_1: R43.1 U11.7(INT)
NetR44_2: R44.2 U11.2(SCK)
NetR45_2: R45.2 U11.4(SDI)

Not connected (* = marked no-connect by the designer): U9 3(IN2P_GPI1)* 4(IN2M_GPO1)*

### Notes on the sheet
- (near U8) Left MIC
- (near U9) Address: 0x4e(1001110)
- (near U11) Address: 0x77(1110111)

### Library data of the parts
C28-C30 C33 C34 C39 = CMP-0089959-1: as C24 on sheet TIDA-010997_Sensors
C31 C37 C38 = CMP-0007336-5: CAP, CERM, 10 uF, 16 V, +/- 20%, X5R, 0603; Manufacturer: MuRata; TaMin_C: -55°C; Polarized: N; SizeAreaWB_mm2: 4.68; Value1: Unknown; U/M: EA; Value: 10uF; TaMax_C: 85°C; SizeZ_mm: 1; SizeX_mm: 1.6; SizeY_mm: 0.8; SizeArea_mm2: 1.28; Cap_F: 10µF; AEC Category: Q200
C32 C35 C36 C40 C41 = CMP-0006286-2: as C27 on sheet TIDA-010997_Sensors
C42 C43 = CMP-0860555-1: as C6 on sheet TIDA-010997_Sensors
J8-J10 = CMP-0055086-1: as J6 on sheet TIDA-010997_Connector
R36 = CMP-0026745-1: RES, 100 k, 1%, 0.063 W, 0402; Manufacturer: Samsung Electro-Mechanics; Power_W: 63mW; TempCo: 100 ppm/C; U/M: EA; Value: 100k; EIA_Code: E96; SizeX_mm: 1; SizeY_mm: 0.5; SizeZ_mm: 0.6; Value2: 0.063W; AEC Qualified: N; VDC_V: 80V; AEC Category: Q200
R37-R39 R42-R45 = CMP-0026822-3: as R2 on sheet TIDA-010997_Sensors
TP1 TP2 = CMP-0055163-2: Test Point, Compact, Grey, TH; Manufacturer: Keystone Electronics; ContactFinish: Silver; CT: TRUE; CNHeader: FALSE
U8 = CMP-0120060-1: 60 Hz ~ 20 kHz Digital, I²S Microphone MEMS (Silicon) 1.65 V ~ 3.63 V Omnidirectional (-26 ±1dB @ 94dB SPL) Solder Pads; Manufacturer: TDK InvenSense; SizeZ_mm: 0.98mm; AEC Qualified: No; Current: 230-490uA; Direction: Omidirectional; Frequency_Fixed: 60-20000Hz; Max Supply Voltage: 3.63V; Min Supply Voltage: 1.65V
U9 = CMP-0123801-1: 2-Channel, 768-kHz, Burr-BrownTM Audio ADC; Manufacturer: Texas Instruments; SizeZ_mm: 0.8mm; AEC Qualified: No; Data Polarity: Single Ended/Differential; Interface: I2C,I2S; Max Supply Voltage: 3.6V; Min Supply Voltage: 1.65V; Number Of Channels: 2; Resolution: 32bits; Sampling Rate: 768ksps; Standoff Height: 0mm; TaMax_C: +125°C; TaMin_C: -40°C; TJmax_C: +150°C
U10 = CMP-0089487-2: 77Hz ~ 20kHz Analog Microphone MEMS (Silicon) 1.5V ~ 3.63V Omnidirectional (-37.5dB ±1dB @ 94dB SPL) Solder Pads; Manufacturer: TDK; SizeZ_mm: 1.3mm; Operating Supply Voltage: 1.5-3.63V; Current: 155µA; Frequency_Fixed: 77-20000Hz; Direction: Omidirectional; AEC Qualified: No
U11 = CMP-0126884-1: BMP384 Series 1.8 V 300 to 1250 hPa ±0.5 hPa Barometric Pressure Sensor - LGA-10; Manufacturer: Bosch Sensortec; SizeZ_mm: 1mm; AEC Qualified: No; Max Supply Voltage: 3.6V; Min Supply Voltage: 1.2V; Operating Supply Current: 700uA; Port Style: No Port; Sensor Output: SPI

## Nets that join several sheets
3V3_EVM: TIDA-010997_Connector (6 pins), TIDA-010997_Sensors (10 pins), TIDA-010997_Audio_Air_pressure (9 pins)
GND: TIDA-010997_Connector (5 pins), TIDA-010997_Sensors (35 pins), TIDA-010997_Audio_Air_pressure (26 pins)
Air_INTR: TIDA-010997_Connector (J2/J4.39), TIDA-010997_Audio_Air_pressure (R43.2)
Audio_GPIO: TIDA-010997_Connector (J2/J4.40), TIDA-010997_Audio_Air_pressure (U9.11)
HDC_INTR: TIDA-010997_Connector (J2/J4.31), TIDA-010997_Sensors (R4.2)
I2C_SCL: TIDA-010997_Connector (J1/J3.9 R17.1), TIDA-010997_Sensors (R6.1 R21.2), TIDA-010997_Audio_Air_pressure (R39.2 R44.1)
I2C_SDA: TIDA-010997_Connector (J1/J3.10 R18.1), TIDA-010997_Sensors (R8.1 R22.2), TIDA-010997_Audio_Air_pressure (R38.2 R45.1)
I2S_SCLK: TIDA-010997_Connector (J1/J3.28), TIDA-010997_Audio_Air_pressure (J8.2)
I2S_SD: TIDA-010997_Connector (J1/J3.30), TIDA-010997_Audio_Air_pressure (J9.2)
I2S_WS: TIDA-010997_Connector (J1/J3.27), TIDA-010997_Audio_Air_pressure (J10.2)
INERT_INTR1: TIDA-010997_Connector (J2/J4.35), TIDA-010997_Sensors (R32.1)
INERT_INTR2: TIDA-010997_Connector (J2/J4.33), TIDA-010997_Sensors (R33.1)
Magnet_INTR: TIDA-010997_Connector (J2/J4.36), TIDA-010997_Sensors (R35.1)
OPT_INTR: TIDA-010997_Connector (J2/J4.32), TIDA-010997_Sensors (R23.2)
PIR1_IN: TIDA-010997_Connector (J7.2), TIDA-010997_Sensors (R13.2)
PIR2_IN: TIDA-010997_Connector (J6.2), TIDA-010997_Sensors (R29.2)
SPI_CLK: TIDA-010997_Connector (J1/J3.7), TIDA-010997_Sensors (U6.13 U7.1)
SPI_CS_1: TIDA-010997_Connector (J2/J4.18), TIDA-010997_Sensors (U6.12)
SPI_CS_2: TIDA-010997_Connector (J2/J4.19), TIDA-010997_Sensors (U7.4)
SPI_MISO: TIDA-010997_Connector (J2/J4.14), TIDA-010997_Sensors (U6.1 U7.3)
SPI_MOSI: TIDA-010997_Connector (J2/J4.15), TIDA-010997_Sensors (U6.14 U7.2)

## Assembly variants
001: all parts fitted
